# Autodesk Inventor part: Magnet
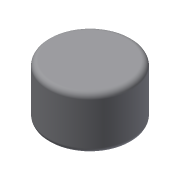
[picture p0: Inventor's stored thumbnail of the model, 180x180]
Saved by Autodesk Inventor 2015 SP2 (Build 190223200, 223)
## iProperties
Created: 2017-07
Material: Generisch
Document SubType Name: Modeling
Designer: UR
Density: 1 g/cm^3
Appearance: Vorgabe
Part Number: Magnet
Description: Ø8 x 5
Author: UR
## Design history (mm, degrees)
sketch "Skizze1"
  geometry: C1 r 4 at (0, 0); 1 further point
  constraints: 1 centre point, 1 coincident
  dimensions: "d0" = 8 diameter of C1
extrude "Extrusion1" new body sketch "Skizze1" distance "d1" = 5; taper "d2" = 0 deg
fillet "Rundung1" dims "d3" = 0.5
node "Volumenkörper1"
